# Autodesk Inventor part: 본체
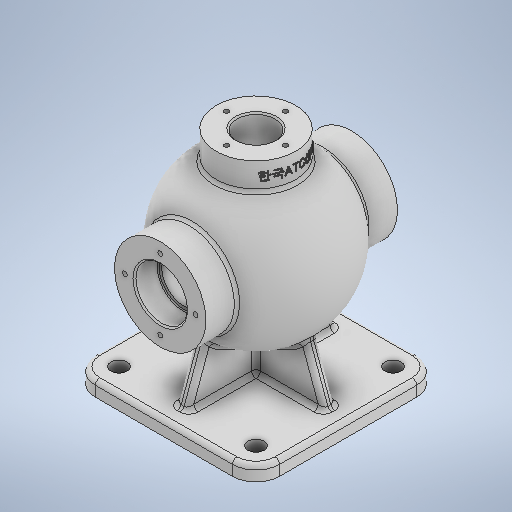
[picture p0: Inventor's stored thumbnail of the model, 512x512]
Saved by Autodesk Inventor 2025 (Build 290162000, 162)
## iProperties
Created: 2024-07
Part Number: 본체
Material: 일반
Document SubType Name: Modeling
Designer: onair
Density: 1 g/cm^3
Appearance: 기본값
Author: onair
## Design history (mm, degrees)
sketch "스케치1"
  geometry: L1 (46.5, -62.5)-(-46.5, -62.5); L2 (-62.5, -46.5)-(-62.5, 46.5); L3 (-46.5, 62.5)-(46.5, 62.5); L4 (62.5, 46.5)-(62.5, -46.5); L5 (62.5, -62.5)-(-62.5, 62.5); L6 (-62.5, -62.5)-(62.5, 62.5); A1 r 16 centre (-46.5, 46.5) between (-46.5, 62.5) and (-62.5, 46.5); A2 r 16 centre (-46.5, -46.5) between (-62.5, -46.5) and (-46.5, -62.5); A3 r 16 centre (46.5, -46.5) between (46.5, -62.5) and (62.5, -46.5); A4 r 16 centre (46.5, 46.5) between (62.5, 46.5) and (46.5, 62.5); 1 further point
  constraints: 12 end point, 8 point on circle, 8 point on line, 8 tangent, 4 centre point, 3 equal radius, 2 midpoint, 2 parallel, 1 horizontal, 1 perpendicular
  dimensions: "d0" = 125 distance of L5.end L6.end; "d1" = 125 distance of L6.start L5.end; "d2" = 16 radius of A1
extrude "돌출1" new body sketch "스케치1" distance "d3" = 10; taper "d4" = 0 deg
sketch "스케치2"
  geometry: A1 r 16 centre (-46.5, -46.5) between (-62.5, -46.5) and (-46.5, -62.5) reference; A2 r 16 centre (-46.5, 46.5) between (-46.5, 62.5) and (-62.5, 46.5) reference; A3 r 16 centre (46.5, 46.5) between (62.5, 46.5) and (46.5, 62.5) reference; A4 r 16 centre (46.5, -46.5) between (46.5, -62.5) and (62.5, -46.5) reference; 5 further points
  constraints: 4 coincident
hole "구멍1" sketch "스케치2" at (-46.5, -46.5), (-46.5, 46.5), (46.5, 46.5), (46.5, -46.5) diameter "d5" = 11; stored, may be unused: countersink angle "d9" = 90 deg, drill point angle "d11" = 120 deg; dims "d6" = 8, "d7" = 4, "d8" = 2, "d10" = 10
sketch "스케치3"
  geometry: L1 (46.5, 10)-(-46.5, 10) reference; L2 (-87.5, 0)-(87.5, 0) reference; L3 (0, -13.909)-(0, 83.453) reference; L4 (-62.5, 0)-(-62.5, 10) reference; L5 (41, 10)-(52, 10) reference; L6 (41, 10)-(52, 10) reference; L7 (-52, 10)-(-41, 10) reference; L8 (-52, 10)-(-41, 10) reference; L9 (-46.5, 10)-(46.5, 10) reference; L10 (46.5, 10)-(62.5, 10) reference; L11 (62.5, 10)-(46.5, 10) reference; L12 (46.5, 10)-(-46.5, 10) reference; L13 (-46.5, 10)-(-62.5, 10) reference; L14 (-62.5, 10)-(-46.5, 10) reference; L15 (-50.5, 10)-(-27.819, 72.316); L16 (50.5, 10)-(27.819, 72.316); L17 (-27.819, 72.316)-(27.819, 72.316); L18 (-50.5, 10)-(50.5, 10); 5 further points; 1 other entity
  constraints: 8 end point, 2 horizontal, 2 symmetric about line, 1 point on line, 1 other
  dimensions: "d15" = 12 distance from line of L4 L15.start; "d16" = 20 deg angle of L15 L4; "d17" = 55.63776 distance of L15.end L16.end
extrude "돌출2" join sketch "스케치3" stored distance "d18" = 8; taper "d19" = 0 deg
sketch "스케치4"
  geometry: L1 (-14.463, 0)-(86.779, 0) reference; L2 (10, -4)-(10, 4) reference; L3 (10, 4)-(10, -4) reference; L4 (10, 52)-(10, 41) reference; L5 (10, -41)-(10, -52) reference; L6 (10, -41)-(10, -52) reference; L7 (10, 52)-(10, 41) reference; L8 (10, 62.5)-(10, 46.5) reference; L9 (10, 46.5)-(10, -46.5) reference; L10 (10, -46.5)-(10, -62.5) reference; L11 (10, -62.5)-(10, -46.5) reference; L12 (10, -46.5)-(10, 46.5) reference; L13 (10, 46.5)-(10, 62.5) reference; L14 (0, 62.5)-(10, 62.5) reference; L15 (0, 62.5)-(10, 62.5) reference; L16 (10, 50.5)-(64.513, 30.659); L17 (10, -50.5)-(64.513, -30.659); L18 (64.513, 30.659)-(64.513, -30.659); 7 further points
  constraints: 6 end point, 2 symmetric about line, 1 point on line, 1 vertical
  dimensions: "d20" = 20 deg angle of L16 L14; "d21" = 12 distance from line of L14 L16.start; "d22" = 61.31806 distance of L16.end L17.end
extrude "돌출3" join sketch "스케치4" stored distance "d23" = 8; taper "d24" = 0 deg
sketch "스케치5"
  geometry: L1 (0, -27.8)-(0, 166.8) reference; L2 (0, 139)-(0, 31); A1 r 54 centre (0, 85) between (0, 31) and (0, 139); 1 further point
  constraints: 3 point on line, 2 end point, 2 point on circle, 1 centre point, 1 collinear
  dimensions: "d25" = 108 diameter of A1; "d26" = 85 distance of point (0, 0) A1.centre
revolve "회전1" sketch "스케치5" stored, may be unused: angle "d27" = 360 deg
sketch "스케치6"
  geometry: C1 r 31 at (0, 85); C2 r 15 at (0, 85); A1 r 54 centre (0, 85) between (37.385, 46.034) and (-37.385, 46.034) reference; 1 further point
  constraints: 2 centre point, 2 coincident
  dimensions: "d28" = 62 diameter of C1; "d29" = 30 diameter of C2
extrude "돌출4" join sketch "스케치6" stored distance "d30" = 130; taper "d31" = 0 deg
extrude "돌출5" cut sketch "스케치6" extent not by distance; stored distance "d32" = 0; taper "d33" = 0 deg
sketch "스케치7" dims "d59" = 48
  geometry: C1 r 31 at (0, 0) reference; C2 r 17.5 at (0, 0); 3 further points
  constraints: 2 coincident, 1 centre point, 1 horizontal alignment, 2 other
  dimensions: "d34" = 35 diameter of C2
sketch "스케치8"
  geometry: C1 r 17.5 at (0, 0) reference; 1 further point
extrude "돌출6" cut sketch "스케치7" distance "d35" = 16; taper "d36" = 0 deg
extrude "돌출7" cut sketch "스케치8" distance "d37" = 16; taper "d38" = 0 deg
node "작업 평면1"
sketch "스케치9" dims "d42" = 40
  geometry: C1 r 27 at (0, 0); C2 r 13 at (0, 0); 3 further points
  constraints: 3 coincident, 2 centre point, 1 vertical alignment, 2 other
  dimensions: "d40" = 54 diameter of C1; "d41" = 26 diameter of C2
extrude "돌출8" join sketch "스케치9" stored distance "d43" = 16; taper "d44" = 0 deg
sketch "스케치10"
  geometry: L1 (102.5, -65)-(67.5, -65) reference; L2 (67.5, 65)-(102.5, 65) reference; L3 (85, 89.341)-(85, -91.884); L4 (-30, 0)-(180, 0) reference; L5 (129, 0)-(41, 0); A1 r 44 centre (85, 0) between (41, 0) and (129, 0); 2 further points
  constraints: 5 point on line, 4 end point, 2 point on circle, 1 centre point, 1 collinear, 1 midpoint, 1 vertical
  dimensions: "d45" = 44 radius of A1
revolve "회전2" sketch "스케치10" stored, may be unused: angle "d46" = 360 deg
extrude "돌출9" cut sketch "스케치9" stored distance "d47" = 10; taper "d48" = 0 deg
hole "구멍2" sketch "스케치9" diameter "d49" = 3.242; stored, may be unused: countersink angle "d53" = 90 deg, drill point angle "d55" = 120 deg; dims "d50" = 9, "d51" = 4, "d52" = 2, "d54" = 11
fillet "모깎기1" dims "d70" = 0.6
chamfer "모따기1" distance "d71" = 1; stored, may be unused: second distance "d72" = 2, angle "d73" = 45 deg
hole "구멍4" sketch "스케치7" diameter "d74" = 3.242; stored, may be unused: countersink angle "d78" = 90 deg, drill point angle "d80" = 120 deg; dims "d75" = 12, "d76" = 4, "d77" = 2, "d79" = 15
fillet "모깎기2" dims "d84" = 3
fillet "모깎기4" dims "d86" = 3
fillet "모깎기5" dims "d87" = 3
fillet "모깎기6" dims "d88" = 3
sketch "스케치11"
  geometry: L1 (150, -27)-(150, 27) reference; L2 (-30, 0)-(180, 0) reference; 2 further points
  constraints: 1 point on line, 1 other
  dimensions: "d89" = 9 distance from line of L1 point (141, 0)
feature "엠보싱1" sketch "스케치11" dims "d0" = 125, "d1" = 125, "d2" = 16, "d90" = 0.5, "d91" = 0
feature "ѻ耀ѽ耀ѿ耀ҁ耀҃耀҅耀҇耀҉耀" dims "d0" = 125, "d1" = 125, "d2" = 16, "d3" = 10, "d4" = 0, "d5" = 11, "d6" = 8, "d7" = 4, "d8" = 2, "d9" = 90 deg, "d10" = 10, "d11" = 120 deg, "d15" = 12, "d16" = 20 deg, "d17" = 55.63776, "d18" = 8, "d19" = 0, "d20" = 20 deg, "d21" = 12, "d22" = 61.31806, "d23" = 8, "d24" = 0, "d25" = 108, "d26" = 85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
node "솔리드1"
pattern_circular "원형 패턴1" dims angle "d57" = 360 deg
pattern_circular "원형 패턴3" dims angle "d82" = 360 deg
mirror "미러2"
node "투영된 루프1"
node "투영된 루프2"
node "투영된 루프3"
feature "A9D066F2-1C7D-4E18-AEED-F7BC21143FA4" dims "d5" = 11, "d6" = 8, "d7" = 4, "d8" = 2, "d9" = 90 deg, "d10" = 10, "d11" = 120 deg
